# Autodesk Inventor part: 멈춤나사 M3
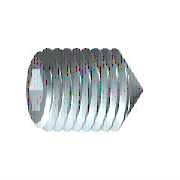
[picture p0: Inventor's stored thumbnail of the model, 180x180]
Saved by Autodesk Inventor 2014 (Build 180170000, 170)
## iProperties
IsCustomPart: 1
Created: 2012-02
Part Number: 멈춤나사 M3
Material: 강철, 연강
Description: 6각 소켓 머리 없는 멈춤 나사
Document SubType Name: Modeling
Standard: KS B 1028
Designer: mduedu
Standards Organization: KS
Language: ko-KR
Size Designation: 원추점 M3x6
Categories: <MemberInstance><Categories><Category DisplayName="조임쇠" InternalName="e4da775c-781d-43d5-af7c-5136215cf5a6" Mnemonic="FSTN"><Category DisplayName="볼트" InternalN
Density: 1 g/cm^3
Appearance: Yellow
Author: mduedu
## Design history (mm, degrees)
sketch "스케치1"
  geometry: L1 (0, 0)-(3.5, 0); L2 (6, 0.866)-(6, 1.5); L3 (6, 1.5)-(0, 1.5); L4 (6, 0.866)-(4, 0.866); L5 (4, 0.866)-(3.5, 0); L6 (0, -0.3)-(0, 1.8) reference; L7 (0, 1.5)-(0, 0)
  constraints: 13 end point, 3 parallel, 1 collinear, 1 perpendicular, 1 point on line
  dimensions: "d0" = 2 distance of L2.start L4.end (= INTI); "d1" = 60 deg angle of L5 L1; "d2" = 3 diameter of L3 L1 (= NND); "d3" = 1.73205 diameter of L4 L1 (= 1.1547 x SW); "d5" = 6 distance from line of L2 L3.end (= NLG)
revolve "본체" sketch "스케치1" stored, may be unused: angle "d6" = 90 deg
sketch "스케치2"
  geometry: L1 (-0.433, 0.75)-(0.433, 0.75); L2 (0.433, 0.75)-(0.866, 0); L3 (0.866, 0)-(0.433, -0.75); L4 (0.433, -0.75)-(-0.433, -0.75); L5 (-0.433, -0.75)-(-0.866, 0); L6 (-0.866, 0)-(-0.433, 0.75); 3 further points
  constraints: 12 end point, 1 coincident, 1 horizontal, 13 other
extrude "슬롯" join sketch "스케치2" taper "d7" = 0 deg; stored distance "d21" = 10
workaxis "Work Axis1"
workplane "Work Plane1"
body "Solid1"
feature "스레드" dims "d12" = 6 (= NLG), "d13" = 0
chamfer "모따기1" distance "d8" = 1.35 (computed from NND, SPD, FAWI); stored, may be unused: angle "d9" = 45 deg (= FAWI), second distance "d34" = 1.35 (computed from NND, SPD, FAWI)
chamfer "모따기2" distance "d10" = 0.30673 (= -0.5 x GD1 + 0.5 x NND); stored, may be unused: angle "d11" = 45 deg (= FAWI), second distance "d35" = 0.30673 (= -0.5 x GD1 + 0.5 x NND)
other parameters: "NND" = 3 [user parameter; used in 5 equation terms], "NLG" = 6 [user parameter; used in 2 equation terms], "INTI" = 2 [user parameter; used in 1 equation term], "FAWI" = 45 deg [user parameter; used in 4 equation terms], "SW" = 1.5 [user parameter; used in 2 equation terms], "GD1" = 2.38655 (= THREADDIA - 1.2269 x PTC) [user parameter; used in 2 equation terms], "d4" = 0, "FAWI1" = 45 deg [user parameter], "SPD" = 0.3 [user parameter; used in 2 equation terms], "d36" = 0, "d37" = 0, "GUL" = 0.30673 (= 0.61345 x PTC) [user parameter], "TOA" = 30 deg [user parameter], "THREADDIA" = 3 [user parameter; used in 1 equation term], "PTC" = 0.5 [user parameter; used in 4 equation terms], "GAL" = 0.30673 (= 0.61345 x PTC) [user parameter], "E0" = 1.7325 (= 1.155 x SW) [user parameter]
